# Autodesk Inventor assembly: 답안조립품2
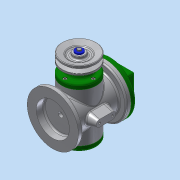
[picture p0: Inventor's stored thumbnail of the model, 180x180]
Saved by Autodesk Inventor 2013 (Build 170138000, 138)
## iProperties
Created: 2018-02
Part Number: 답안조립품2
Document SubType Name: Assembly
Designer: Administrator
Author: Administrator
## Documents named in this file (18)
- C:\Users\Administrator\Desktop\480208V1009\답안조립품2.iam
- C:\Users\Administrator\Desktop\480208V1009\본체.ipt
- C:\Users\Administrator\Desktop\480208V1009\E-링.ipt
- C:\Users\Administrator\Desktop\480208V1009\V-벨트풀리.ipt
- C:\Users\Administrator\Desktop\480208V1009\덮개.ipt
- C:\Users\Administrator\Desktop\480208V1009\뒤커버.ipt
- C:\Users\Administrator\Desktop\480208V1009\링크.ipt
- C:\Users\Administrator\Desktop\480208V1009\베어링 17 x 40 x 12.ipt
- C:\Users\Administrator\Desktop\480208V1009\볼트 M4 x 8.ipt
- C:\Users\Administrator\Desktop\480208V1009\볼트 M4 x 10.ipt
- C:\Users\Administrator\Desktop\480208V1009\슬라이더.ipt
- C:\Users\Administrator\Desktop\480208V1009\앞커버.ipt
- C:\Users\Administrator\Desktop\480208V1009\오일 실 17 30 8.ipt
- C:\Users\Administrator\Desktop\480208V1009\와셔 4x16.ipt
- C:\Users\Administrator\Desktop\480208V1009\클레비스 핀 6 x 22.ipt
- 클레비스 핀 6 x 22.ipt
- C:\Users\Administrator\Desktop\480208V1009\키 4 x 4 x 12.ipt
- C:\Users\Administrator\Desktop\480208V1009\편심축.ipt
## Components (2 placed, 2 different names)
1. E-링:1
2. V-벨트풀리:1
